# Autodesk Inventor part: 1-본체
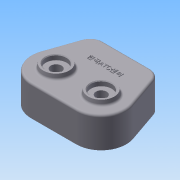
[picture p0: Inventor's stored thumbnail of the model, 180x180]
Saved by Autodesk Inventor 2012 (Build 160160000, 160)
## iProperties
Created: 2014-12
Part Number: 1-본체
Material: 알루미늄-6061
Document SubType Name: Modeling
Designer: Owner
Density: 2.71 g/cm^3
Mass: 613.304 g
Surface Area: 666.548 cm^2
Volume: 226.311 cm^3
Author: Owner
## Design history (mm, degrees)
sketch "스케치1"
  geometry: L1 (-47, 36)-(47, 36); L2 (-32.527, -32.527)-(0, 0); L3 (32.527, -32.527)-(0, 0); L4 (-32.527, -68.527)-(32.527, -68.527); L5 (-47, 36)-(-66.565, -20.803); L6 (47, 36)-(66.565, -20.803); A1 r 46 centre (0, 0) between (-32.527, -32.527) and (32.527, -32.527); A2 r 36 centre (-32.527, -32.527) between (-32.527, -68.527) and (-66.565, -20.803); A3 r 36 centre (32.527, -32.527) between (32.527, -68.527) and (66.565, -20.803); 2 further points
  constraints: 12 end point, 6 point on circle, 3 centre point, 3 tangent, 1 coincident, 1 equal radius, 1 horizontal, 1 horizontal alignment, 1 midpoint, 1 parallel, 1 vertical alignment
  dimensions: "d0" = 46 radius of A1; "d1" = 94 distance of L1.start L1.end; "d2" = 36 vertical distance of point (0, 0) L1.end; "d3" = 36 radius of A2; "d4" = 90 deg angle of L3 L2
extrude "돌출1" new body sketch "스케치1" distance "d5" = 44; taper "d6" = 0 deg
sketch "스케치2"
  geometry: C1 r 20 at (-32.527, -32.527); C2 r 20 at (32.527, -32.527); A1 r 36 centre (32.527, -32.527) between (32.527, -68.527) and (66.565, -20.803) reference; A2 r 36 centre (-32.527, -32.527) between (-66.565, -20.803) and (-32.527, -68.527) reference; 1 further point
  constraints: 2 centre point, 2 coincident, 1 equal radius
  dimensions: "d7" = 40 diameter of C2
extrude "돌출2" join sketch "스케치2" distance "d8" = 7; taper "d9" = -10 deg
sketch "스케치3"
  geometry: L1 (47, 36)-(66.565, -20.803) reference; L2 (-47, 36)-(47, 36) reference; L3 (-66.565, -20.803)-(-47, 36) reference; L4 (32.527, -68.527)-(-32.527, -68.527) reference; L5 (-43.434, 31)-(43.434, 31); L6 (43.434, 31)-(61.837, -22.432); L7 (-43.434, 31)-(-61.837, -22.432); L8 (-32.527, -63.527)-(32.527, -63.527); A1 r 36 centre (32.527, -32.527) between (32.527, -68.527) and (66.565, -20.803) reference; A2 r 36 centre (-32.527, -32.527) between (-66.565, -20.803) and (-32.527, -68.527) reference; A3 r 31 centre (-32.527, -32.527) between (-61.837, -22.432) and (-32.527, -63.527); A4 r 31 centre (32.527, -32.527) between (32.527, -63.527) and (61.837, -22.432); 1 further point
  constraints: 8 end point, 4 point on circle, 4 tangent, 3 parallel, 2 centre point, 2 coincident, 1 equal radius
  dimensions: "d10" = 31 radius of A3; "d12" = 5 distance between parallel lines of L2 L5
extrude "돌출3" cut sketch "스케치3" distance "d13" = 34; taper "d14" = 0 deg
sketch "스케치4"
  geometry: C1 r 24 at (0, 0); C2 r 24 at (-32.527, -32.527); C3 r 24 at (32.527, -32.527); A1 r 31 centre (-32.527, -32.527) between (-61.837, -22.432) and (-32.527, -63.527) reference; A2 r 31 centre (32.527, -32.527) between (32.527, -63.527) and (61.837, -22.432) reference; 1 further point
  constraints: 3 centre point, 3 coincident, 2 equal radius
  dimensions: "d15" = 48 diameter of C1
extrude "돌출4" join sketch "스케치4" distance "d16" = 11; taper "d17" = 0 deg
hole "구멍1" diameter "d20" = 15.5; stored, may be unused: countersink angle "d24" = 90 deg, drill point angle "d26" = 118 deg; dims "d18" = 10, "d19" = 10, "d21" = 6, "d22" = 30, "d23" = 7, "d25" = 8
hole "구멍2" diameter "d29" = 15.5; stored, may be unused: countersink angle "d33" = 90 deg, drill point angle "d35" = 118 deg; dims "d27" = 10, "d28" = 10, "d30" = 6, "d31" = 30, "d32" = 7, "d34" = 8
hole "구멍3" diameter "d38" = 20; stored, may be unused: countersink angle "d42" = 90 deg, drill point angle "d44" = 0 deg; dims "d39" = 6, "d40" = 40, "d41" = 12, "d43" = 15, "d45" = 10, "d46" = 10
hole "구멍4" diameter "d49" = 35; stored, may be unused: countersink angle "d53" = 90 deg, drill point angle "d55" = 0 deg; dims "d47" = 10, "d48" = 10, "d50" = 6, "d51" = 30, "d52" = 7, "d54" = 11
hole "구멍5" diameter "d58" = 35; stored, may be unused: countersink angle "d62" = 90 deg, drill point angle "d64" = 0 deg; dims "d56" = 10, "d57" = 10, "d59" = 6, "d60" = 30, "d61" = 7, "d63" = 11
sketch "스케치5"
  geometry: L1 (-47, 36)-(47, 36) reference; 2 further points
  constraints: 1 vertical alignment, 1 other
  dimensions: "d65" = 30 distance from line of L1 point (0, 6)
feature "엠보싱1" sketch "스케치5" dims "d0" = 46, "d1" = 94, "d2" = 36, "d3" = 36, "d4" = 90 deg, "d66" = 1, "d67" = 0
fillet "모깎기1" dims "d68" = 18, "d80" = 0.1, "d81" = 0.3, "d86" = 13
sketch "스케치6"
  geometry: L1 (-34.162, 36)-(34.162, 36) reference; L2 (-61.837, -22.432)-(-43.434, 31) reference; L3 (43.434, 31)-(61.837, -22.432) reference; L4 (32.527, -63.527)-(-32.527, -63.527) reference; A1 r 8 centre (51.7, 7) between (49.095, 14.564) and (54.305, -0.564); A2 r 8 centre (-51.7, 7) between (-54.305, -0.564) and (-49.095, 14.564); A3 r 8 centre (0, -63.527) between (8, -63.527) and (-8, -63.527); 1 further point
  constraints: 8 point on line, 6 point on circle, 3 centre point, 2 equal radius, 1 horizontal alignment, 1 midpoint
  dimensions: "d69" = 8 radius of A1; "d70" = 29 distance from line of L1 A1.centre
extrude "돌출5" join sketch "스케치6" stored distance "d71" = 11; taper "d72" = 0 deg
sketch "스케치7"
  geometry: A1 r 8 centre (-51.7, 7) between (-54.305, -0.564) and (-49.095, 14.564) reference; A2 r 8 centre (51.7, 7) between (49.095, 14.564) and (54.305, -0.564) reference; A3 r 8 centre (0, -63.527) between (8, -63.527) and (-8, -63.527) reference; 4 further points
  constraints: 3 coincident
hole "구멍6" sketch "스케치7" at (-51.7, 7), (51.7, 7), (0, -63.527) diameter "d73" = 2.459; stored, may be unused: countersink angle "d77" = 90 deg, drill point angle "d79" = 118 deg; dims "d74" = 20, "d75" = 30, "d76" = 7, "d78" = 23
chamfer "모따기1" distance "d82" = 1; stored, may be unused: second distance "d83" = 2, angle "d84" = 45 deg
fillet "모깎기2" dims "d85" = 3
node "솔리드1"
